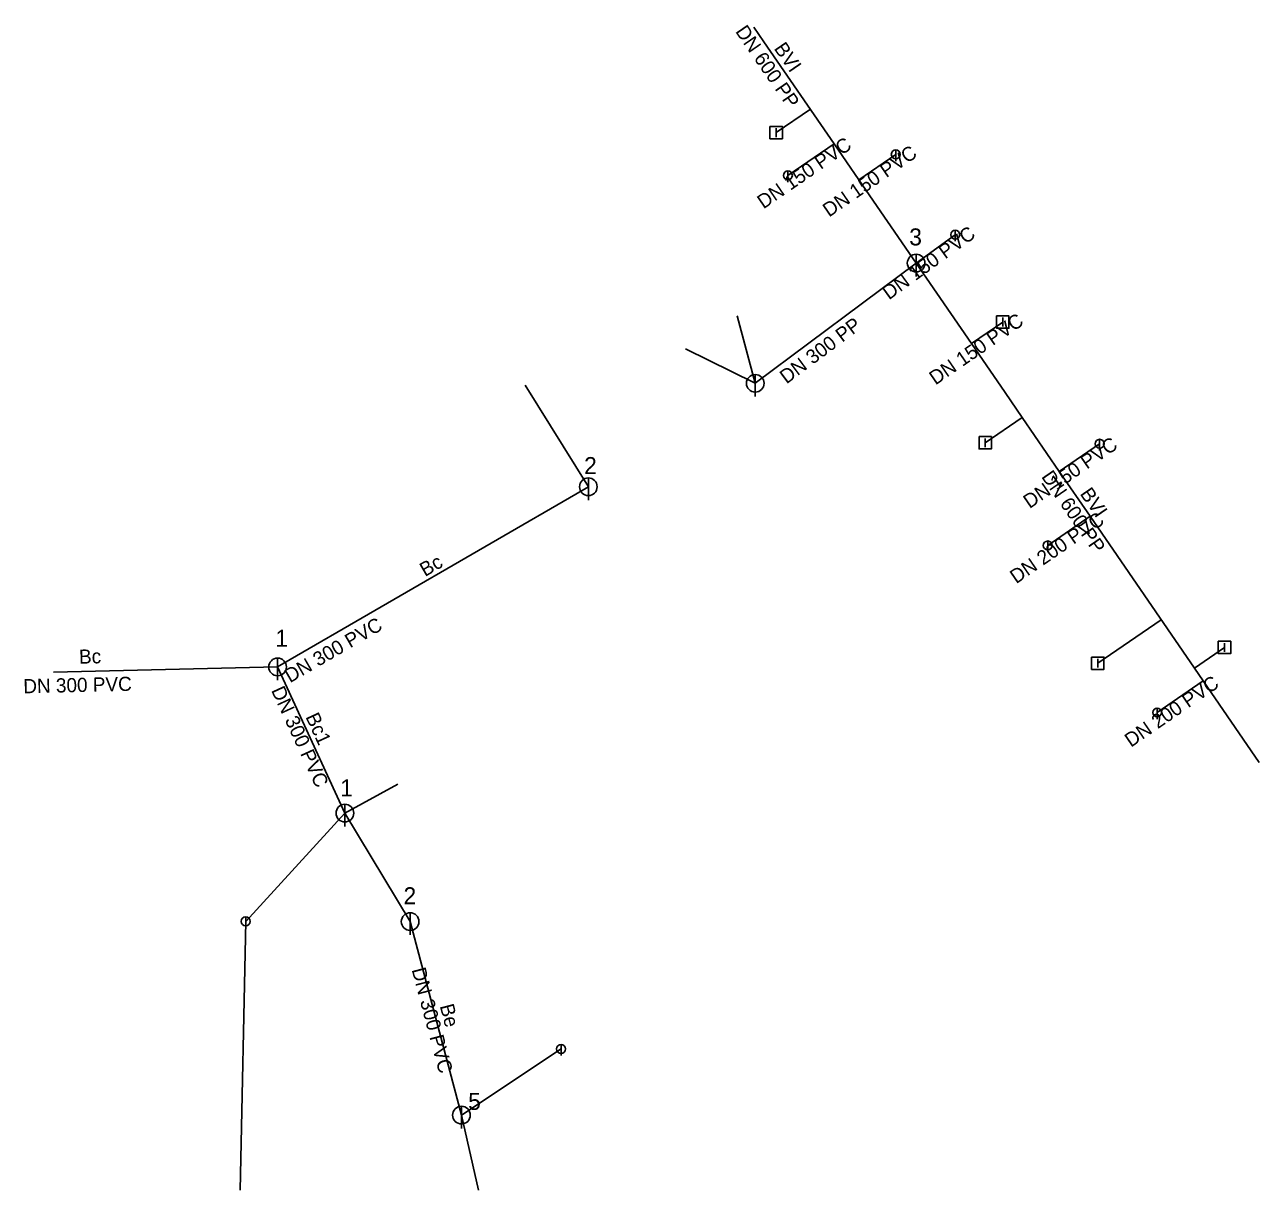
# Model space of a CAD drawing. Extents: x -464789 to -464649, y -1094693 to -1094561.
import ezdxf

# ---------------------------------------------------------------- set-up
doc = ezdxf.new("R2010")
doc.units = 0
for name, color, linetype in [('_pripojka_kanal_destova_prevzato_z_dokumentace_', 7, 'Continuous'), ('_pripojka_kanal_jednotna_prevzato_z_dokumentace_', 7, 'Continuous'), ('_stoka_jednotna_smvak_prevzato_z_dokumentace_', 7, 'Continuous'), ('Default', 7, 'Continuous'), ('MoLevel 119', 7, 'Continuous'), ('MoLevel 120', 7, 'Continuous'), ('MoLevel 126', 7, 'Continuous'), ('MoLevel 130', 7, 'Continuous'), ('MoLevel 57', 7, 'Continuous'), ('MoLevel 63', 7, 'Continuous'), ('MoLevel 68', 7, 'Continuous'), ('MoLevel 69', 7, 'Continuous')]:
    doc.layers.add(name, color=color, linetype=linetype)

# ---------------------------------------------------------------- blocks, each defined once
blk = doc.blocks.new('_vpust_')
at = {"layer": 'Default'}
blk.add_line((0, 0.000025), (0, -0.000025), dxfattribs=at)
blk.add_lwpolyline([(-0.000035, 0.000035), (0.000035, 0.000035), (0.000035, -0.000035), (-0.000035, -0.000035), (-0.000035, 0.000035)], dxfattribs=at)
blk = doc.blocks.new('_sachta_kanal_prip_')
at = {"layer": 'Default'}
blk.add_line((0, 0.00005), (0, -0.000075), dxfattribs=at)
blk.add_circle((0, 0), 0.00005, dxfattribs=at)
blk = doc.blocks.new('_sachta_kanal_prevzato_z_dokumentace_')
at = {"layer": 'Default'}
blk.add_line((0, 0.00005), (0, -0.000075), dxfattribs=at)
blk.add_circle((0, 0), 0.00005, dxfattribs=at)

msp = doc.modelspace()

# ---------------------------------------------------------------- linework, layer by layer
at = {"layer": '_pripojka_kanal_destova_prevzato_z_dokumentace_'}
for p, q in [((-464704.18, -1094572.89), (-464700.31, -1094570.23)), ((-464678.53, -1094594.33), (-464682.07, -1094596.77)), ((-464680.5, -1094608), (-464676.33, -1094605.12)), ((-464667.76, -1094632.96), (-464660.58, -1094628.03)), ((-464653.41, -1094631.17), (-464656.81, -1094633.51))]:
    msp.add_line(p, q, dxfattribs=at)
at = {"layer": '_pripojka_kanal_jednotna_prevzato_z_dokumentace_'}
for p, q in [((-464702.85, -1094577.73), (-464697.63, -1094574.14)), ((-464690.64, -1094575.35), (-464694.82, -1094578.23)), ((-464683.9, -1094584.44), (-464688.33, -1094587.66)), ((-464708.61, -1094593.61), (-464706.55, -1094601.27)), ((-464714.43, -1094597.35), (-464706.55, -1094601.27)), ((-464732.61, -1094601.49), (-464725.45, -1094612.98)), ((-464667.55, -1094608.11), (-464672.12, -1094611.25)), ((-464673.43, -1094619.62), (-464668.63, -1094616.32)), ((-464661.04, -1094638.54), (-464655.82, -1094634.95)), ((-464747.03, -1094646.65), (-464753.02, -1094649.93)), ((-464764.25, -1094662.18), (-464753.02, -1094649.93)), ((-464764.86, -1094692.63), (-464764.25, -1094662.18)), ((-464728.54, -1094676.63), (-464739.82, -1094684.12))]:
    msp.add_line(p, q, dxfattribs=at)
at = {"layer": '_stoka_jednotna_smvak_prevzato_z_dokumentace_'}
for p, q in [((-464706.55, -1094601.27), (-464688.33, -1094587.66)), ((-464725.45, -1094612.98), (-464760.64, -1094633.38)), ((-464760.64, -1094633.38), (-464786.01, -1094633.98)), ((-464753.02, -1094649.93), (-464760.64, -1094633.38)), ((-464745.63, -1094662.21), (-464753.02, -1094649.93)), ((-464745.63, -1094662.21), (-464739.82, -1094684.12)), ((-464739.82, -1094684.12), (-464737.88, -1094692.63))]:
    msp.add_line(p, q, dxfattribs=at)
for points in [[(-464688.33, -1094587.66), (-464694.82, -1094578.23), (-464697.63, -1094574.14), (-464705.56, -1094562.6), (-464706.71, -1094560.93)], [(-464649.47, -1094644.18), (-464655.82, -1094634.95), (-464656.81, -1094633.51), (-464668.63, -1094616.32), (-464672.12, -1094611.25), (-464676.33, -1094605.12), (-464678.26, -1094602.32), (-464682.07, -1094596.77), (-464688.33, -1094587.66)]]:
    msp.add_lwpolyline(points, dxfattribs=at)

# ---------------------------------------------------------------- block references
at = {"layer": 'MoLevel 119', "xscale": 20000, "yscale": 20000}
for p in [(-464688.33, -1094587.66), (-464706.55, -1094601.27), (-464725.45, -1094612.98), (-464760.64, -1094633.38), (-464753.02, -1094649.93), (-464745.63, -1094662.21), (-464739.82, -1094684.12)]:
    msp.add_blockref('_sachta_kanal_prevzato_z_dokumentace_', p, dxfattribs=at)
at = {"layer": 'MoLevel 57', "xscale": 10000, "yscale": 10000}
for p in [(-464690.64, -1094575.35), (-464702.85, -1094577.73), (-464683.9, -1094584.44), (-464667.55, -1094608.11), (-464673.43, -1094619.62), (-464661.04, -1094638.54), (-464764.25, -1094662.18), (-464728.54, -1094676.63)]:
    msp.add_blockref('_sachta_kanal_prip_', p, dxfattribs=at)
at = {"layer": 'MoLevel 63', "xscale": 20000, "yscale": 20000}
for p in [(-464704.18, -1094572.89), (-464678.53, -1094594.33), (-464680.5, -1094608), (-464653.41, -1094631.17), (-464667.76, -1094632.96)]:
    msp.add_blockref('_vpust_', p, dxfattribs=at)

# ---------------------------------------------------------------- texts
at = {"layer": 'MoLevel 120'}
for s, p in [('3', (-464689.11, -1094585.66)), ('2', (-464725.93, -1094611.55)), ('1', (-464760.89, -1094631.09)), ('1', (-464753.55, -1094648.03)), ('2', (-464746.38, -1094660.25)), ('5', (-464739.06, -1094683.53))]:
    msp.add_text(s, height=1.93, dxfattribs=at).set_placement(p)
at = {"layer": 'MoLevel 126'}
for s, rotation, p in [('DN 150 PVC', 34.5178, (-464705.62, -1094581.58)), ('DN 150 PVC', 34.5667, (-464698.2, -1094582.51)), ('DN 150 PVC', 36.012, (-464691.41, -1094591.88)), ('DN 150 PVC', 34.4926, (-464675.49, -1094615.51)), ('DN 200 PVC', 34.5085, (-464677, -1094624.02)), ('DN 200 PVC', 34.5178, (-464664.01, -1094642.53))]:
    msp.add_text(s, height=1.605, rotation=rotation, dxfattribs=at).set_placement(p)
at = {"layer": 'MoLevel 130'}
msp.add_text('DN 150 PVC', height=1.605, rotation=34.5772, dxfattribs=at).set_placement((-464686.14, -1094601.52))
at = {"layer": 'MoLevel 68'}
for s, rotation, p in [('DN 600 PP', 304.4959, (-464708.86, -1094561.43)), ('DN 300 PP', 36.758, (-464703.01, -1094601.4)), ('DN 600 PP', 304.5421, (-464674.21, -1094611.84)), ('DN 300 PVC', 30.1013, (-464759.24, -1094635.23)), ('DN 300 PVC', 1.3458, (-464789.42, -1094636.37)), ('DN 300 PVC', 294.7224, (-464761.4, -1094636.02)), ('DN 300 PVC', 284.8516, (-464745.47, -1094667.64))]:
    msp.add_text(s, height=1.605, rotation=rotation, dxfattribs=at).set_placement(p)
at = {"layer": 'MoLevel 69'}
for s, rotation, p in [('BVI', 304.4959, (-464704.49, -1094563.36)), ('BVI', 304.5421, (-464669.84, -1094613.77)), ('Bc', 30.1013, (-464743.95, -1094623.21)), ('Bc', 1.3458, (-464783.11, -1094633.02)), ('Bc1', 294.7224, (-464757.51, -1094639.02)), ('Be', 284.8516, (-464742.29, -1094671.76))]:
    msp.add_text(s, height=1.605, rotation=rotation, dxfattribs=at).set_placement(p)

doc.saveas('drawing.dxf')
